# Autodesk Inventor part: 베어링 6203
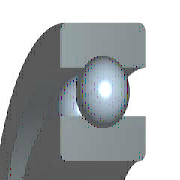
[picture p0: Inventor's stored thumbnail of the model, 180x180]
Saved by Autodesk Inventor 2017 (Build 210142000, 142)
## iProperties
Created: 2012-02
Part Number: 베어링 6203
Material: 강철, 연강
Description: 깊은 그루브 볼 베어링
Document SubType Name: Modeling
Standard: KS B 2023
Designer: mduedu
Standards Organization: KS
Language: ko-KR
Size Designation: 6203 - 17 x 40 x 12
Categories: <MemberInstance><Categories><Category DisplayName="샤프트 부품" InternalName="7f7aeb1f-a693-4053-b835-cee3144e0d98" Mnemonic="SHFT"><Category DisplayName="베어링" Inter
Density: 7.85 g/cm^3
Mass: 64.8982 g
Surface Area: 64.3582 cm^2
Volume: 8.26729 cm^3
Appearance: 노란색
IsCustomPart: 1
Author: mduedu
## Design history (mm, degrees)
sketch "스케치" dims "d0" = 5.98 (= -0.26 x WD + 0.26 x BD)
  geometry: L1 (3.01, 14.25)-(8.99, 14.25); L2 (6, 14.25)-(6, 11.26); L3 (6, 14.25)-(6, 17.24); L4 (3.778, 12.249)-(0, 12.249); L5 (0, 8.5)-(12, 8.5); L6 (3.778, 16.251)-(0, 16.251); L7 (0, 20)-(12, 20); L8 (12, 8.5)-(12, 12.249); L9 (8.222, 12.249)-(12, 12.249); L10 (8.222, 16.251)-(12, 16.251); L11 (12, 20)-(12, 16.251); L12 (-1.4, 0)-(8.4, 0) reference; L13 (0, -0.3)-(0, 5.3) reference
  constraints: 22 end point, 4 point on line, 2 collinear, 2 perpendicular, 2 symmetric about line, 1 midpoint, 1 parallel, 14 other
  dimensions: "d9" = 17 diameter of L5 L12 (= WD); "d11" = 40 diameter of L7 L12 (= BD); "d12" = 12 distance between parallel lines of L8 L13 (= KB); "d13" = 24.498 diameter of L9 L12 (= 0.326 x BD + 0.674 x WD)
revolve "본체" stored, may be unused: angle "d6" = 90 deg
revolve "볼" stored, may be unused: angle "d7" = 90 deg
pattern_circular "IDS_ARRAYBALL[SIMPL:T]" dims angle "d3" = 360 deg
body "Solid1"
fillet "모깎기1" dims "d1" = 0.6 (= KRS)
other parameters: "WD" = 17 [user parameter; used in 5 equation terms], "BD" = 40 [user parameter; used in 5 equation terms], "KB" = 12 [user parameter; used in 1 equation term], "KRS" = 0.6 [user parameter; used in 1 equation term], "d4" = 0, "d5" = 0, "d8" = 0, "d14" = 0, "d15" = 0, "BBA" = 0 [user parameter], "BC0" = 4750000 [user parameter], "BC" = 9560000 [user parameter], "WR" = 8.5 (= 0.5 x WD) [user parameter]
